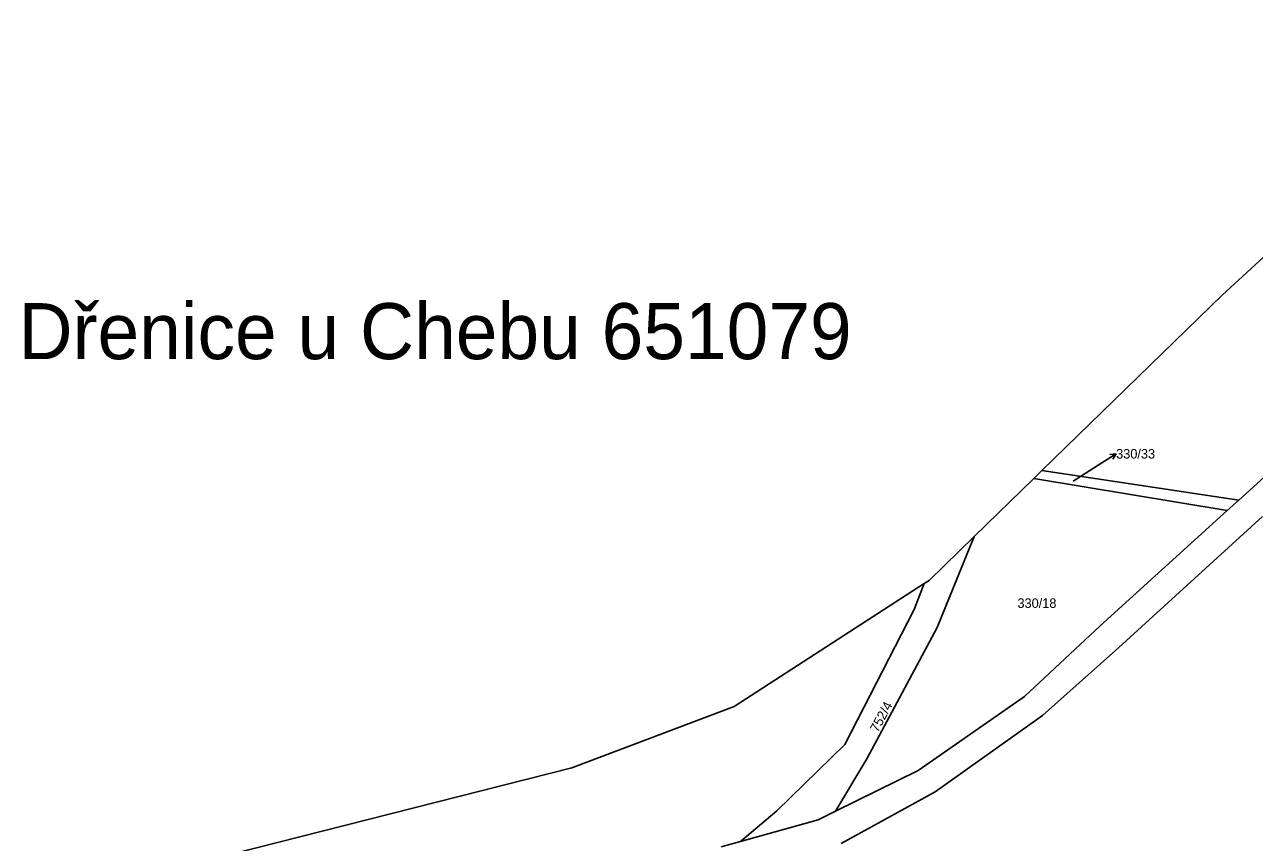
# Model space of a CAD drawing. Extents: x -887272 to -880188, y -1026687 to -1021896.
# Drawn here: x -883035.4 to -882815.9, y -1023862.8 to -1023716.8 of the extents above; entities that cross this region are included whole.
import ezdxf

# ---------------------------------------------------------------- set-up
doc = ezdxf.new("R2010")
doc.units = 0
for name, color, linetype in [('Hranice parcel', 7, 'Continuous'), ('Parcelní čísla', 7, 'Continuous'), ('Pop  PČ popisy', 7, 'Continuous')]:
    doc.layers.add(name, color=color, linetype=linetype)

msp = doc.modelspace()

# ---------------------------------------------------------------- linework, layer by layer
at = {"layer": 'Hranice parcel'}
for p, q in [((-882818.72, -1023801.69), (-882807.36, -1023791.35)), ((-882855.29, -1023797.82), (-882853.85, -1023796.42)), ((-882853.85, -1023796.42), (-882818.72, -1023801.69)), ((-882855.29, -1023797.82), (-882865.91, -1023808.16)), ((-882820.78, -1023803.56), (-882855.29, -1023797.82)), ((-882818.72, -1023801.69), (-882820.78, -1023803.56)), ((-882907.61, -1023862.61), (-882911.11, -1023863.59))]:
    msp.add_line(p, q, dxfattribs=at)
for points in [[(-882726.3, -1023648.88), (-882721.13, -1023653.25), (-882736.57, -1023677.46), (-882773.39, -1023720.75), (-882821.66, -1023765.08), (-882853.85, -1023796.42)], [(-882890.66, -1023857.2), (-882875.91, -1023849.94), (-882856.93, -1023836.72), (-882843.42, -1023824.16), (-882820.78, -1023803.56)], [(-882814.51, -1023804.61), (-882840.14, -1023827.98), (-882853.74, -1023840.13), (-882872.92, -1023853.76), (-882889.66, -1023862.97)], [(-882865.91, -1023808.16), (-882872.54, -1023824.44), (-882885.08, -1023847.86), (-882890.66, -1023857.2)], [(-882874.84, -1023816.57), (-882873.99, -1023816.02), (-882865.91, -1023808.16)], [(-883023.64, -1023870.22), (-883018.61, -1023870), (-882937.74, -1023849.5), (-882908.79, -1023838.53), (-882874.84, -1023816.57)], [(-882907.61, -1023862.61), (-882901.16, -1023857.16), (-882889, -1023845.3), (-882876.62, -1023821.24), (-882874.84, -1023816.57)], [(-882890.66, -1023857.2), (-882893.78, -1023858.74), (-882907.61, -1023862.61)]]:
    msp.add_lwpolyline(points, dxfattribs=at)
at = {"layer": 'Pop  PČ popisy'}
for p, q in [((-882848.26, -1023798.31), (-882843.13, -1023795.04)), ((-882843.13, -1023795.04), (-882840.58, -1023793.45)), ((-882840.58, -1023793.45), (-882841.7, -1023793.56)), ((-882840.58, -1023793.45), (-882841.17, -1023794.41))]:
    msp.add_line(p, q, dxfattribs=at)

# ---------------------------------------------------------------- texts
at = {"layer": 'Parcelní čísla'}
for s, p in [('330/33', (-882840.6, -1023794.27)), ('330/18', (-882858.21, -1023820.93))]:
    msp.add_text(s, height=1.7, dxfattribs=at).set_placement(p)
msp.add_text('752/4', height=1.7, rotation=62, dxfattribs=at).set_placement((-882883.11, -1023843.28))
at = {"layer": 'Pop  PČ popisy'}
msp.add_text('Dřenice u Chebu 651079', height=10, dxfattribs=at).set_placement((-883036.48, -1023776.53))

doc.saveas('drawing.dxf')
